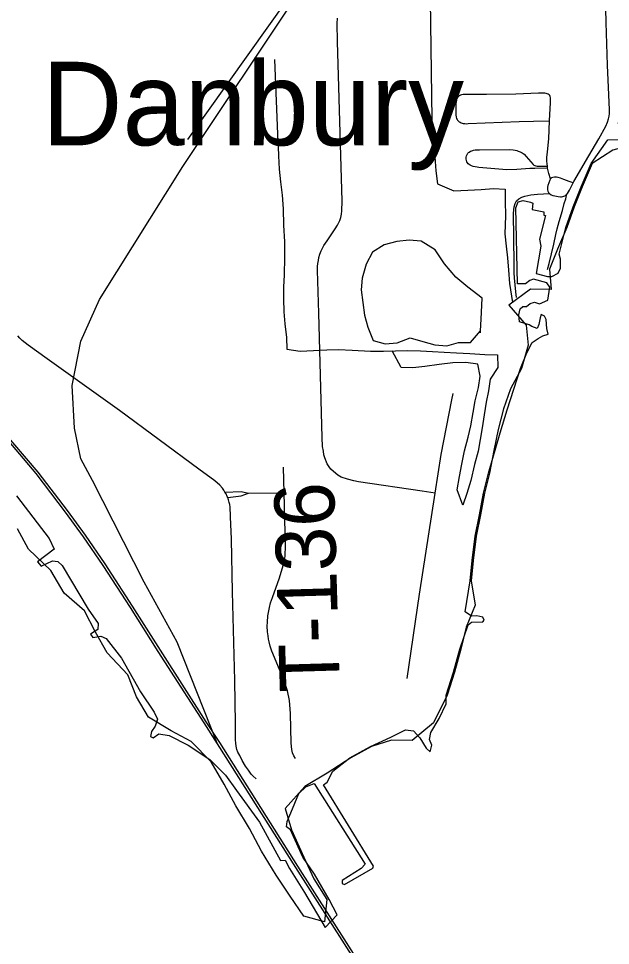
# Model space of a CAD drawing. Extents: x -12 to 34, y 0 to 22.
# Drawn here: x 2.674 to 3.233, y 14.753 to 15.63 of the extents above; entities that cross this region are included whole.
import ezdxf

# ---------------------------------------------------------------- set-up
doc = ezdxf.new("R2010")
doc.units = 0
for name, color, linetype in [('GM_X_Airport_Location_Class_2', 7, 'Continuous'), ('GM_X_Corporation', 7, 'Continuous'), ('GM_X_County_Road_Text', 7, 'Continuous'), ('GM_X_Major_River', 7, 'Continuous'), ('GM_X_Minor_Lake', 7, 'Continuous'), ('GM_X_Minor_River', 7, 'Continuous'), ('GM_X_Section_Text', 7, 'Continuous')]:
    doc.layers.add(name, color=color, linetype=linetype)

msp = doc.modelspace()

# ---------------------------------------------------------------- linework, layer by layer
at = {"layer": 'GM_X_Airport_Location_Class_2'}
msp.add_lwpolyline([(2.67184, 15.17844), (2.6913, 15.15289), (2.70271, 15.13814), (2.70742, 15.12811), (2.69169, 15.11611), (2.69504, 15.11206), (2.70585, 15.1169), (2.71076, 15.11651), (2.7151, 15.11258), (2.73947, 15.07129), (2.74904, 15.05769), (2.74872, 15.05222), (2.7418, 15.04772), (2.74405, 15.0445), (2.75161, 15.04579), (2.7566, 15.04369), (2.77092, 15.02503), (2.7891, 14.99334), (2.80181, 14.97388), (2.80503, 14.96728), (2.80293, 14.96085), (2.7994, 14.95554), (2.79843, 14.95087), (2.80116, 14.94975), (2.80631, 14.95361), (2.81612, 14.952), (2.83414, 14.94267), (2.85457, 14.92916), (2.86953, 14.91435), (2.87983, 14.90004), (2.90156, 14.86996), (2.92156, 14.83369), (2.92597, 14.83402), (2.93004, 14.82623), (2.94428, 14.80351), (2.96361, 14.77028), (2.97513, 14.78249), (2.96733, 14.79673), (2.95343, 14.8208), (2.94268, 14.8369), (2.93092, 14.86275), (2.92711, 14.86552), (2.92783, 14.87054), (2.93105, 14.87878), (2.93881, 14.89705), (2.94526, 14.90326), (2.95338, 14.9066), (3.00139, 14.83017), (2.99781, 14.82611), (2.97989, 14.81489), (2.97989, 14.81202), (2.98181, 14.81106), (3.00879, 14.82659), (3.00927, 14.8285), (2.96222, 14.90541), (2.96556, 14.90779), (2.97082, 14.91806), (2.98709, 14.93081), (3.00644, 14.94146), (3.02582, 14.95024), (3.03957, 14.95712), (3.04716, 14.95641), (3.05333, 14.9497), (3.05914, 14.93981), (3.06313, 14.93646), (3.06447, 14.94278), (3.06245, 14.94811), (3.06356, 14.95476), (3.07159, 14.96803), (3.07811, 14.9819), (3.07818, 14.99014), (3.08501, 15.01181), (3.09108, 15.03348), (3.09886, 15.05661), (3.10207, 15.05918), (3.1128, 15.05945), (3.11391, 15.06083), (3.1128, 15.06367), (3.10704, 15.06507), (3.10207, 15.06468), (3.09593, 15.06896), (3.10094, 15.09812), (3.10284, 15.1175), (3.1055, 15.14032), (3.10967, 15.16047), (3.11346, 15.181), (3.11801, 15.20001), (3.12931, 15.23803), (3.13587, 15.25972), (3.14837, 15.29886), (3.15453, 15.31367), (3.15932, 15.3235), (3.16512, 15.32728), (3.16965, 15.3298), (3.1747, 15.33131), (3.17344, 15.33661), (3.17268, 15.34518), (3.17117, 15.34846), (3.16789, 15.34997), (3.16688, 15.34695), (3.16562, 15.34039), (3.16411, 15.33686), (3.15906, 15.33863), (3.15654, 15.34014), (3.14747, 15.34291), (3.14697, 15.34972), (3.14797, 15.35527), (3.15074, 15.35753), (3.15403, 15.35753), (3.15755, 15.36031), (3.16159, 15.36157), (3.16638, 15.36006), (3.17419, 15.36359), (3.17628, 15.37585), (3.17344, 15.37997), (3.16058, 15.3835), (3.1573, 15.38199), (3.15301, 15.37896), (3.14545, 15.37896), (3.14394, 15.45081), (3.14621, 15.45636), (3.151, 15.45787), (3.1578, 15.45611), (3.16007, 15.45536), (3.15957, 15.4493), (3.17041, 15.44704), (3.17041, 15.44376), (3.17192, 15.44351), (3.16638, 15.42132), (3.16764, 15.41451), (3.1631, 15.3888), (3.17394, 15.38577), (3.17797, 15.38577), (3.18402, 15.38905), (3.18629, 15.39384), (3.18629, 15.40241), (3.18503, 15.40695), (3.19125, 15.43232), (3.19808, 15.45171), (3.20567, 15.47072), (3.21516, 15.49278), (3.23107, 15.51509), (3.24768, 15.51557)], dxfattribs=at)
msp.add_lwpolyline([(2.67184, 15.17844), (2.6913, 15.15289), (2.70271, 15.13814), (2.70742, 15.12811), (2.69169, 15.11611), (2.69504, 15.11206), (2.70585, 15.1169), (2.71076, 15.11651), (2.7151, 15.11258), (2.73947, 15.07129), (2.74904, 15.05769), (2.74872, 15.05222), (2.7418, 15.04772), (2.74405, 15.0445), (2.75161, 15.04579), (2.7566, 15.04369), (2.77092, 15.02503), (2.7891, 14.99334), (2.80181, 14.97388), (2.80503, 14.96728), (2.80293, 14.96085), (2.7994, 14.95554), (2.79843, 14.95087), (2.80116, 14.94975), (2.80631, 14.95361), (2.81612, 14.952), (2.83414, 14.94267), (2.85457, 14.92916), (2.86953, 14.91435), (2.87983, 14.90004), (2.90156, 14.86996), (2.92156, 14.83369), (2.92597, 14.83402), (2.93004, 14.82623), (2.94428, 14.80351), (2.96361, 14.77028), (2.97513, 14.78249), (2.96733, 14.79673), (2.95343, 14.8208), (2.94268, 14.8369), (2.93092, 14.86275), (2.92711, 14.86552), (2.92783, 14.87054), (2.93105, 14.87878), (2.93881, 14.89705), (2.94526, 14.90326), (2.95338, 14.9066), (3.00139, 14.83017), (2.99781, 14.82611), (2.97989, 14.81489), (2.97989, 14.81202), (2.98181, 14.81106), (3.00879, 14.82659), (3.00927, 14.8285), (2.96222, 14.90541), (2.96556, 14.90779), (2.97082, 14.91806), (2.98709, 14.93081), (3.00644, 14.94146), (3.02582, 14.95024), (3.03957, 14.95712), (3.04716, 14.95641), (3.05333, 14.9497), (3.05914, 14.93981), (3.06313, 14.93646), (3.06447, 14.94278), (3.06245, 14.94811), (3.06356, 14.95476), (3.07159, 14.96803), (3.07811, 14.9819), (3.07818, 14.99014), (3.08501, 15.01181), (3.09108, 15.03348), (3.09886, 15.05661), (3.10207, 15.05918), (3.1128, 15.05945), (3.11391, 15.06083), (3.1128, 15.06367), (3.10704, 15.06507), (3.10207, 15.06468), (3.09593, 15.06896), (3.10094, 15.09812), (3.10284, 15.1175), (3.1055, 15.14032), (3.10967, 15.16047), (3.11346, 15.181), (3.11801, 15.20001), (3.12931, 15.23803), (3.13587, 15.25972), (3.14837, 15.29886), (3.15453, 15.31367), (3.15932, 15.3235), (3.16512, 15.32728), (3.16965, 15.3298), (3.1747, 15.33131), (3.17344, 15.33661), (3.17268, 15.34518), (3.17117, 15.34846), (3.16789, 15.34997), (3.16688, 15.34695), (3.16562, 15.34039), (3.16411, 15.33686), (3.15906, 15.33863), (3.15654, 15.34014), (3.14747, 15.34291), (3.14697, 15.34972), (3.14797, 15.35527), (3.15074, 15.35753), (3.15403, 15.35753), (3.15755, 15.36031), (3.16159, 15.36157), (3.16638, 15.36006), (3.17419, 15.36359), (3.17628, 15.37585), (3.17344, 15.37997), (3.16058, 15.3835), (3.1573, 15.38199), (3.15301, 15.37896), (3.14545, 15.37896), (3.14394, 15.45081), (3.14621, 15.45636), (3.151, 15.45787), (3.1578, 15.45611), (3.16007, 15.45536), (3.15957, 15.4493), (3.17041, 15.44704), (3.17041, 15.44376), (3.17192, 15.44351), (3.16638, 15.42132), (3.16764, 15.41451), (3.1631, 15.3888), (3.17394, 15.38577), (3.17797, 15.38577), (3.18402, 15.38905), (3.18629, 15.39384), (3.18629, 15.40241), (3.18503, 15.40695), (3.19125, 15.43232), (3.19808, 15.45171), (3.20567, 15.47072), (3.21516, 15.49278), (3.23107, 15.51509), (3.24768, 15.51557)], dxfattribs=at)
at = {"layer": 'GM_X_Corporation'}
for points in [[(2.86142, 14.94456), (2.82373, 15.04019), (2.79236, 15.09674), (2.74349, 15.19316), (2.73263, 15.21353), (2.72655, 15.24239), (2.72448, 15.28279), (2.73263, 15.32489), (2.75028, 15.36427), (2.82913, 15.4899), (3.04858, 15.81881), (3.37589, 16.27795), (3.61021, 16.61802), (3.67642, 16.69541), (3.72177, 16.72971), (3.76196, 16.75383), (3.83492, 16.78166), (3.88685, 16.80022), (4.00803, 16.82248), (4.81753, 16.84573)], [(2.6571, 15.24175), (2.69179, 15.20095), (2.71974, 15.1645), (2.7366, 15.14121), (2.75523, 15.11407), (2.78122, 15.07412), (2.80751, 15.03244), (2.85094, 14.96497), (2.86361, 14.94525), (2.9375, 14.8284), (2.98366, 14.75611), (3.12808, 14.52914)], [(2.65536, 15.24021), (2.68998, 15.1995), (2.71787, 15.16311), (2.7347, 15.13987), (2.75329, 15.11278), (2.77926, 15.07287), (2.80554, 15.0312), (2.84898, 14.96372), (2.86164, 14.944), (2.93553, 14.82715), (2.9817, 14.75486), (3.12611, 14.5279)]]:
    msp.add_lwpolyline(points, dxfattribs=at)
at = {"layer": 'GM_X_Major_River'}
for p, q in [((3.17409, 15.48829), (3.17382, 15.49009)), ((2.92486, 15.18148), (2.92416, 15.20561)), ((2.89113, 15.18098), (2.92486, 15.18148))]:
    msp.add_line(p, q, dxfattribs=at)
for points in [[(3.19824, 15.4744), (3.19891, 15.47568), (3.21298, 15.49988), (3.22255, 15.51614), (3.22896, 15.52791), (3.23072, 15.53196), (3.23169, 15.53503), (3.23221, 15.53741), (3.23256, 15.54004), (3.23265, 15.54338), (3.23203, 15.55762), (3.2308, 15.58564), (3.22946, 15.6261), (3.22401, 15.8412), (3.22259, 15.88303)], [(3.06766, 15.18095), (3.05543, 15.18293), (2.99519, 15.19189), (2.99063, 15.19276), (2.98477, 15.19414), (2.97893, 15.19627), (2.97559, 15.19793), (2.97364, 15.19947), (2.96916, 15.20375), (2.96745, 15.20606), (2.96564, 15.20886), (2.96324, 15.21455), (2.96252, 15.2174), (2.96196, 15.22061), (2.96128, 15.22517), (2.96079, 15.23367), (2.95777, 15.3512), (2.95651, 15.39167), (2.95658, 15.39525), (2.95683, 15.39809), (2.95726, 15.40095), (2.95781, 15.40388), (2.95874, 15.40695), (2.95991, 15.41004), (2.96151, 15.41337), (2.96256, 15.41536), (2.96545, 15.41966), (2.97321, 15.43088), (2.97531, 15.43445), (2.97747, 15.4389), (2.97848, 15.44161), (2.97888, 15.44329), (2.97907, 15.44486), (2.97939, 15.44793), (2.97988, 15.45724), (2.97546, 15.60814), (2.97515, 15.62521), (2.97539, 15.63014)], [(3.17584, 15.5332), (3.17676, 15.55034), (3.17676, 15.55247), (3.17676, 15.554), (3.1767, 15.55485), (3.17646, 15.55607), (3.17603, 15.55698), (3.17548, 15.55765), (3.17461, 15.55833), (3.17359, 15.55875), (3.17262, 15.55895), (3.1714, 15.55912), (3.16987, 15.55917), (3.16553, 15.55925), (3.14409, 15.55841), (3.1161, 15.5581), (3.10001, 15.55792), (3.09658, 15.5579), (3.0951, 15.55789), (3.09426, 15.55787), (3.09249, 15.55758), (3.09175, 15.55728), (3.09101, 15.55693), (3.09022, 15.55644), (3.08945, 15.55585), (3.08886, 15.55508), (3.08832, 15.5541), (3.08794, 15.55318), (3.08773, 15.55256), (3.08744, 15.55103), (3.08734, 15.54917), (3.08727, 15.54739), (3.08722, 15.54484), (3.0873, 15.5389), (3.08765, 15.53644), (3.08799, 15.53536), (3.08843, 15.53438), (3.08894, 15.53373), (3.08962, 15.53286), (3.09044, 15.53226), (3.0912, 15.53178), (3.09229, 15.53117), (3.09405, 15.53068), (3.09571, 15.53047), (3.09761, 15.53036), (3.09902, 15.53041), (3.14704, 15.53245), (3.16084, 15.53283), (3.17584, 15.5332)], [(3.17382, 15.49009), (3.17358, 15.49231), (3.17346, 15.49488), (3.17346, 15.49827), (3.17386, 15.50378), (3.17514, 15.51601), (3.17584, 15.5332)], [(3.17409, 15.48829), (3.16198, 15.48813), (3.15729, 15.48807), (3.14485, 15.48692), (3.13557, 15.48686), (3.10887, 15.48897), (3.10727, 15.48916), (3.10542, 15.48948), (3.10365, 15.48997), (3.10217, 15.49048), (3.10088, 15.49114), (3.09997, 15.49173), (3.09899, 15.49255), (3.09827, 15.49338), (3.0976, 15.49439), (3.09722, 15.49558), (3.09704, 15.49692), (3.09707, 15.49779), (3.09717, 15.49879), (3.09741, 15.49984), (3.09766, 15.50054), (3.09796, 15.50125), (3.09868, 15.5024), (3.09932, 15.50304), (3.09987, 15.50352), (3.10106, 15.50427), (3.1023, 15.5048), (3.10325, 15.50516), (3.10396, 15.50534), (3.1055, 15.50561), (3.10672, 15.5057), (3.10804, 15.50579), (3.10977, 15.50579), (3.13794, 15.50589), (3.14135, 15.50562), (3.14337, 15.50533), (3.14479, 15.50506), (3.14625, 15.50455), (3.14812, 15.50387), (3.14999, 15.50282), (3.15174, 15.50142), (3.15375, 15.49933), (3.1603, 15.49177), (3.16096, 15.4912), (3.16182, 15.49073), (3.16292, 15.4905), (3.16417, 15.49034), (3.16534, 15.49026), (3.1691, 15.49019), (3.17382, 15.49009)], [(3.17678, 15.47826), (3.17533, 15.48335), (3.17409, 15.48829)], [(3.17678, 15.47826), (3.1761, 15.4771), (3.17515, 15.47457), (3.17435, 15.47205), (3.17389, 15.47043), (3.17385, 15.4689), (3.17399, 15.46771), (3.17441, 15.46652), (3.17494, 15.46545), (3.17592, 15.46438), (3.17748, 15.46316), (3.17903, 15.46259), (3.18091, 15.46206), (3.18388, 15.46152), (3.18629, 15.46131), (3.18721, 15.46128), (3.18843, 15.46148), (3.18951, 15.4618), (3.19048, 15.46221), (3.19144, 15.46286), (3.19235, 15.4637)], [(3.19824, 15.4744), (3.19442, 15.4757), (3.18928, 15.47764), (3.18609, 15.47876), (3.1839, 15.47942), (3.18236, 15.47966), (3.18069, 15.4797), (3.17907, 15.47952), (3.17781, 15.47907), (3.17678, 15.47826)], [(3.19235, 15.4637), (3.19298, 15.46449), (3.19464, 15.46746), (3.19824, 15.4744)], [(3.14478, 15.36593), (3.14409, 15.37132), (3.14261, 15.38449), (3.14232, 15.38941), (3.14232, 15.39827), (3.14189, 15.44562), (3.14239, 15.45183), (3.14324, 15.45477), (3.14473, 15.45741), (3.14697, 15.45945), (3.14967, 15.46091), (3.15254, 15.46183), (3.1583, 15.463), (3.1644, 15.46372), (3.17592, 15.46438)], [(3.17409, 15.39251), (3.17544, 15.39821), (3.17981, 15.41657), (3.18181, 15.42554), (3.18308, 15.43102), (3.18482, 15.43805), (3.18799, 15.44845), (3.18982, 15.45506), (3.19122, 15.45941), (3.19235, 15.4637)], [(2.87148, 15.17678), (2.87113, 15.17798), (2.87008, 15.18029), (2.86892, 15.1821), (2.86786, 15.1838), (2.86646, 15.18578), (2.864, 15.18851), (2.85925, 15.19267), (2.84411, 15.20371), (2.76905, 15.25916), (2.70091, 15.30813), (2.68277, 15.32111), (2.67985, 15.32322), (2.67727, 15.32532), (2.67494, 15.32766), (2.67295, 15.32989)], [(3.06766, 15.18095), (3.07328, 15.21749), (3.08351, 15.26927), (3.08483, 15.27534)], [(2.86892, 15.1821), (2.88435, 15.18263), (2.89113, 15.18098)], [(2.87148, 15.17678), (2.88437, 15.17842), (2.89113, 15.18098)], [(2.93563, 14.93003), (2.93408, 14.93273), (2.93289, 14.93559), (2.93209, 14.93859), (2.93137, 14.94473), (2.93091, 14.97269), (2.92998, 14.98506), (2.9281, 14.99415), (2.9252, 15.003), (2.91321, 15.03165), (2.91174, 15.03629), (2.91057, 15.0405), (2.90999, 15.04307), (2.90964, 15.04612), (2.90928, 15.04979), (2.90893, 15.05536), (2.90908, 15.0591), (2.90952, 15.06518), (2.91003, 15.06835), (2.91104, 15.07279), (2.91212, 15.07742), (2.91373, 15.0825), (2.92037, 15.10086), (2.92406, 15.11271), (2.92507, 15.11689), (2.92577, 15.12184), (2.92631, 15.13113), (2.92486, 15.18148)], [(3.04114, 15.00567), (3.05302, 15.08553), (3.06766, 15.18095)], [(2.89852, 14.91106), (2.89574, 14.91334), (2.89363, 14.91545), (2.89106, 14.91907), (2.88848, 14.92305), (2.88532, 14.92831), (2.88286, 14.93299), (2.88123, 14.93615), (2.88029, 14.93872), (2.87982, 14.94036), (2.87959, 14.94182), (2.87924, 14.9448), (2.87903, 14.94792), (2.87875, 14.9634), (2.87815, 15.00387), (2.876, 15.08785), (2.87495, 15.13759), (2.87422, 15.15866), (2.87406, 15.16239), (2.87394, 15.16461), (2.87374, 15.16778), (2.87336, 15.17034), (2.87301, 15.17222), (2.87219, 15.17479), (2.87148, 15.17678)]]:
    msp.add_lwpolyline(points, dxfattribs=at)
at = {"layer": 'GM_X_Minor_Lake'}
for points in [[(3.04207, 15.80839), (2.83361, 15.5155)], [(3.06118, 15.78302), (3.06484, 15.51203)], [(2.91562, 15.59114), (2.91905, 15.51248)], [(2.91886, 15.51679), (2.91939, 15.49992), (2.92026, 15.48735), (2.92152, 15.47553), (2.92314, 15.46294), (2.92399, 15.44999), (2.92441, 15.43439), (2.9252, 15.41877), (2.92526, 15.40432), (2.92488, 15.38721), (2.92426, 15.37619), (2.92438, 15.36478), (2.92449, 15.35261), (2.92538, 15.34118), (2.927, 15.32821), (2.92751, 15.31717), (2.94003, 15.31536), (2.9526, 15.31585), (2.96517, 15.31671), (2.97621, 15.31684), (2.98913, 15.31618), (3.00661, 15.31541), (3.01878, 15.31514), (3.03021, 15.31564), (3.04162, 15.31577), (3.05379, 15.3155), (3.06519, 15.31486), (3.07621, 15.31424), (3.08799, 15.3136), (3.10053, 15.31294), (3.1146, 15.31225), (3.12677, 15.31197), (3.12688, 15.2998), (3.11979, 15.28893), (3.11802, 15.27794), (3.11587, 15.26695), (3.11409, 15.2552), (3.11229, 15.24269), (3.11015, 15.23171), (3.10838, 15.22072), (3.10506, 15.20824), (3.1013, 15.19311), (3.0976, 15.18064), (3.09393, 15.16969), (3.08855, 15.18426), (3.09073, 15.19677), (3.09289, 15.20851), (3.09545, 15.22101), (3.09878, 15.23386), (3.10131, 15.24484), (3.10349, 15.25734), (3.10563, 15.26832), (3.10857, 15.28081), (3.11034, 15.2918), (3.10792, 15.30289), (3.09655, 15.30466), (3.08436, 15.30417), (3.07139, 15.30256), (3.05804, 15.30095), (3.04659, 15.29968), (3.03557, 15.29993), (3.02714, 15.31551)], [(3.06481, 15.51412), (3.06738, 15.49891), (3.06823, 15.48596), (3.06985, 15.47337), (3.08531, 15.46694), (3.09864, 15.46741), (3.11121, 15.46827), (3.12303, 15.46915), (3.13405, 15.46852), (3.13379, 15.45712), (3.13425, 15.44341), (3.13349, 15.42631), (3.13475, 15.4145), (3.13603, 15.40344), (3.13691, 15.39201), (3.13816, 15.37943), (3.14078, 15.36127)], [(3.11229, 15.3655), (3.09851, 15.37574), (3.0873, 15.38512), (3.07655, 15.39791), (3.06771, 15.41104), (3.05458, 15.41932), (3.04319, 15.42033), (3.03136, 15.41908), (3.0195, 15.41592), (3.00831, 15.40894), (3.00235, 15.39766), (2.99863, 15.38443), (2.99763, 15.37342), (2.99926, 15.36121)], [(3.11229, 15.3655), (3.09851, 15.37574), (3.0873, 15.38512), (3.07655, 15.39791), (3.06771, 15.41104), (3.05458, 15.41932), (3.04319, 15.42033), (3.03136, 15.41908), (3.0195, 15.41592), (3.00831, 15.40894), (3.00235, 15.39766), (2.99863, 15.38443), (2.99763, 15.37342), (2.99926, 15.36121), (3.0009, 15.34939), (3.00407, 15.3379), (3.00912, 15.32524), (3.02046, 15.32233), (3.0319, 15.32321), (3.04418, 15.32788), (3.0559, 15.32458), (3.06724, 15.32129), (3.07863, 15.32027), (3.08973, 15.32345), (3.10115, 15.32358), (3.11052, 15.3344), (3.11115, 15.34541), (3.11229, 15.3655)], [(2.99926, 15.36121), (3.0009, 15.34939), (3.00407, 15.3379), (3.00912, 15.32524), (3.02046, 15.32233), (3.0319, 15.32321), (3.04418, 15.32788), (3.0559, 15.32458), (3.06724, 15.32129), (3.07863, 15.32027), (3.08973, 15.32345), (3.10115, 15.32358), (3.11052, 15.3344), (3.11115, 15.34541), (3.11229, 15.3655)], [(3.11048, 15.3325), (3.11045, 15.33526)]]:
    msp.add_lwpolyline(points, dxfattribs=at)
at = {"layer": 'GM_X_Minor_River'}
for points in [[(3.25128, 15.55275), (3.26808, 15.54212), (3.27719, 15.52275), (3.2863, 15.50336), (3.26733, 15.51856), (3.25935, 15.53757), (3.24037, 15.53072), (3.25556, 15.51058), (3.23582, 15.50525), (3.21609, 15.4927), (3.2066, 15.47065), (3.19901, 15.45164), (3.19218, 15.43224), (3.18345, 15.41171)], [(3.25136, 15.55224), (3.26808, 15.54212), (3.27719, 15.52275), (3.2863, 15.50336), (3.26733, 15.51856), (3.25935, 15.53757), (3.24037, 15.53072), (3.25556, 15.51058), (3.23582, 15.50525), (3.21609, 15.4927), (3.2066, 15.47065), (3.19901, 15.45164), (3.19218, 15.43224), (3.18345, 15.41171)], [(3.18345, 15.41171), (3.17586, 15.3927), (3.17738, 15.37369), (3.15802, 15.37407), (3.13753, 15.35886), (3.15385, 15.33985), (3.15575, 15.32084), (3.1493, 15.29879), (3.13905, 15.27978), (3.13223, 15.26077), (3.12729, 15.24138), (3.12312, 15.22123), (3.11895, 15.19993), (3.11439, 15.18093), (3.1106, 15.16039), (3.10643, 15.14024), (3.10377, 15.11743), (3.10187, 15.09804), (3.10567, 15.07523), (3.09695, 15.05432), (3.09201, 15.03341), (3.08594, 15.01174), (3.07911, 14.99006), (3.06621, 14.96383), (3.04609, 14.9471), (3.02636, 14.94747), (3.00738, 14.94139), (2.98802, 14.93074), (2.96563, 14.91629), (2.94437, 14.90374), (2.92577, 14.88283), (2.93185, 14.86268), (2.94362, 14.83683), (2.95311, 14.8163), (2.96526, 14.79691), (2.96298, 14.77562), (2.94362, 14.78094), (2.93072, 14.79995), (2.91743, 14.81971), (2.90338, 14.84252), (2.89199, 14.86381), (2.87909, 14.88548), (2.86808, 14.90601), (2.85593, 14.92691), (2.83695, 14.9463), (2.81797, 14.95618), (2.79671, 14.96911), (2.78532, 14.98849), (2.77697, 15.0094), (2.7576, 15.02993), (2.7466, 15.0497), (2.73596, 15.06984), (2.71698, 15.08657), (2.70408, 15.10786), (2.6832, 15.12801), (2.67256, 15.14739)]]:
    msp.add_lwpolyline(points, dxfattribs=at)

# ---------------------------------------------------------------- texts
at = {"layer": 'GM_X_County_Road_Text'}
msp.add_text('T-136', height=0.056818, rotation=91.67298, dxfattribs=at).set_placement((2.97767, 14.99376))
at = {"layer": 'GM_X_Section_Text'}
msp.add_text('Danbury', height=0.078977, rotation=0.00001, dxfattribs=at).set_placement((2.69576, 15.50995))

doc.saveas('drawing.dxf')
